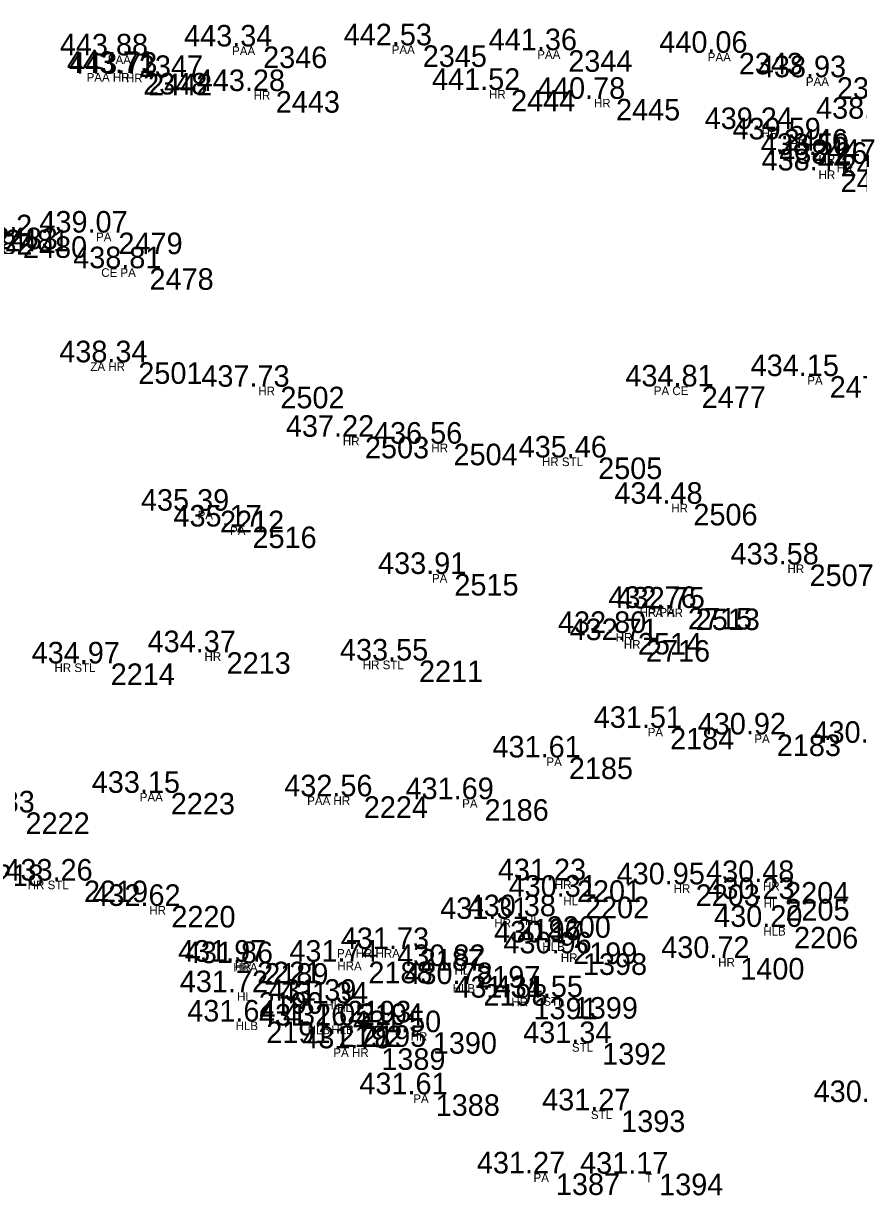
# Model space of a CAD drawing. Extents: x -639390 to -639075, y -1138747 to -1138358.
# Drawn here: x -639325.37 to -639296.34, y -1138603.09 to -1138562.34 of the extents above; entities that cross this region are included whole.
import ezdxf

# ---------------------------------------------------------------- set-up
doc = ezdxf.new("R2010")
doc.units = 0
for name, color, linetype in [('Vrstva 11', 7, 'Continuous'), ('Vrstva 12', 7, 'Continuous'), ('Vrstva 13', 7, 'Continuous'), ('Vrstva 57', 7, 'Continuous')]:
    doc.layers.add(name, color=color, linetype=linetype)

msp = doc.modelspace()

# ---------------------------------------------------------------- linework, layer by layer
at = {"layer": 'Vrstva 11'}
for p, q in [((-639317.32, -1138563.14), (-639317.32, -1138563.14)), ((-639311.77, -1138563.1), (-639311.77, -1138563.1)), ((-639321.64, -1138563.45), (-639321.64, -1138563.45)), ((-639306.71, -1138563.27), (-639306.71, -1138563.27)), ((-639300.78, -1138563.36), (-639300.78, -1138563.36)), ((-639321.49, -1138564.06), (-639321.49, -1138564.06)), ((-639321.32, -1138564.09), (-639321.32, -1138564.09)), ((-639297.37, -1138564.21), (-639297.37, -1138564.21)), ((-639316.88, -1138564.69), (-639316.88, -1138564.69)), ((-639308.7, -1138564.65), (-639308.7, -1138564.65)), ((-639305.05, -1138564.96), (-639305.05, -1138564.96)), ((-639299.22, -1138566.01), (-639299.22, -1138566.01)), ((-639298.25, -1138566.37), (-639298.25, -1138566.37)), ((-639297.24, -1138566.91), (-639297.24, -1138566.91)), ((-639296.61, -1138567.22), (-639296.61, -1138567.22)), ((-639297.24, -1138567.45), (-639297.24, -1138567.45)), ((-639322.35, -1138569.61), (-639322.35, -1138569.61)), ((-639321.27, -1138570.85), (-639321.27, -1138570.85)), ((-639321.66, -1138574.12), (-639321.66, -1138574.12)), ((-639316.72, -1138574.97), (-639316.72, -1138574.97)), ((-639302.07, -1138574.96), (-639302.07, -1138574.96)), ((-639297.62, -1138574.6), (-639297.62, -1138574.6)), ((-639313.78, -1138576.71), (-639313.78, -1138576.71)), ((-639310.7, -1138576.95), (-639310.7, -1138576.95)), ((-639305.67, -1138577.43), (-639305.67, -1138577.43)), ((-639302.36, -1138579.04), (-639302.36, -1138579.04)), ((-639318.82, -1138579.28), (-639318.82, -1138579.28)), ((-639317.69, -1138579.83), (-639317.69, -1138579.83)), ((-639310.67, -1138581.48), (-639310.67, -1138581.48)), ((-639298.32, -1138581.15), (-639298.32, -1138581.15)), ((-639302.55, -1138582.66), (-639302.55, -1138582.66)), ((-639302.28, -1138582.68), (-639302.28, -1138582.68)), ((-639304.29, -1138583.53), (-639304.29, -1138583.53)), ((-639304.01, -1138583.78), (-639304.01, -1138583.78)), ((-639318.59, -1138584.2), (-639318.59, -1138584.2)), ((-639322.62, -1138584.59), (-639322.62, -1138584.59)), ((-639311.9, -1138584.49), (-639311.9, -1138584.49)), ((-639303.17, -1138586.83), (-639303.17, -1138586.83)), ((-639299.46, -1138587.06), (-639299.46, -1138587.06)), ((-639306.69, -1138587.86), (-639306.69, -1138587.86)), ((-639320.53, -1138589.09), (-639320.53, -1138589.09)), ((-639313.82, -1138589.21), (-639313.82, -1138589.21)), ((-639309.62, -1138589.31), (-639309.62, -1138589.31)), ((-639323.55, -1138592.14), (-639323.55, -1138592.14)), ((-639306.41, -1138592.13), (-639306.41, -1138592.13)), ((-639302.28, -1138592.27), (-639302.28, -1138592.27)), ((-639299.17, -1138592.19), (-639299.17, -1138592.19)), ((-639306.13, -1138592.7), (-639306.13, -1138592.7)), ((-639299.16, -1138592.78), (-639299.16, -1138592.78)), ((-639320.51, -1138593.02), (-639320.51, -1138593.02)), ((-639308.51, -1138593.47), (-639308.51, -1138593.47)), ((-639307.46, -1138593.38), (-639307.46, -1138593.38)), ((-639298.86, -1138593.75), (-639298.86, -1138593.75)), ((-639311.87, -1138594.52), (-639311.87, -1138594.52)), ((-639306.54, -1138594.29), (-639306.54, -1138594.29)), ((-639306.2, -1138594.67), (-639306.2, -1138594.67)), ((-639300.73, -1138594.83), (-639300.73, -1138594.83)), ((-639317.53, -1138594.96), (-639317.53, -1138594.96)), ((-639317.28, -1138595.01), (-639317.28, -1138595.01)), ((-639313.66, -1138594.96), (-639313.66, -1138594.96)), ((-639309.91, -1138595.11), (-639309.91, -1138595.11)), ((-639309.66, -1138595.74), (-639309.66, -1138595.74)), ((-639317.47, -1138596.02), (-639317.47, -1138596.02)), ((-639314.4, -1138596.32), (-639314.4, -1138596.32)), ((-639313.99, -1138596.41), (-639313.99, -1138596.41)), ((-639307.92, -1138596.21), (-639307.92, -1138596.21)), ((-639306.52, -1138596.19), (-639306.52, -1138596.19)), ((-639317.21, -1138597.04), (-639317.21, -1138597.04)), ((-639314.7, -1138597.18), (-639314.7, -1138597.18)), ((-639313.88, -1138597.17), (-639313.88, -1138597.17)), ((-639311.42, -1138597.41), (-639311.42, -1138597.41)), ((-639305.53, -1138597.79), (-639305.53, -1138597.79)), ((-639313.21, -1138597.97), (-639313.21, -1138597.97)), ((-639311.32, -1138599.57), (-639311.32, -1138599.57)), ((-639304.87, -1138600.13), (-639304.87, -1138600.13)), ((-639307.14, -1138602.32), (-639307.14, -1138602.32)), ((-639303.55, -1138602.33), (-639303.55, -1138602.33))]:
    msp.add_line(p, q, dxfattribs=at)

# ---------------------------------------------------------------- texts
at = {"layer": 'Vrstva 12'}
for s, p in [('442.53 ', (-639314.239, -1138563.1)), ('443.88 ', (-639324.109, -1138563.45)), ('443.34 ', (-639319.789, -1138563.14)), ('441.36 ', (-639309.196, -1138563.27)), ('440.06 ', (-639303.266, -1138563.36)), ('443.71 ', (-639323.865, -1138564.06)), ('443.73 ', (-639323.789, -1138564.09)), ('438.93 ', (-639299.839, -1138564.21)), ('443.28 ', (-639319.349, -1138564.69)), ('441.52 ', (-639311.169, -1138564.65)), ('440.78 ', (-639307.519, -1138564.96)), ('438.31 ', (-639297.815, -1138565.65)), ('439.24 ', (-639301.689, -1138566.01)), ('439.59 ', (-639300.719, -1138566.37)), ('438.50 ', (-639299.739, -1138566.91)), ('438.44 ', (-639299.709, -1138567.45)), ('438.26 ', (-639299.096, -1138567.22)), ('439.07 ', (-639324.819, -1138569.61)), ('439.62 ', (-639328.139, -1138569.74)), ('438.81 ', (-639323.645, -1138570.85)), ('438.34 ', (-639324.129, -1138574.12)), ('434.15 ', (-639300.09, -1138574.6)), ('437.73 ', (-639319.189, -1138574.97)), ('434.81 ', (-639304.445, -1138574.96)), ('437.22 ', (-639316.249, -1138576.71)), ('436.56 ', (-639313.186, -1138576.95)), ('435.46 ', (-639308.156, -1138577.43)), ('435.39 ', (-639321.289, -1138579.28)), ('434.48 ', (-639304.829, -1138579.04)), ('435.17 ', (-639320.159, -1138579.83)), ('433.58 ', (-639300.789, -1138581.15)), ('433.91 ', (-639313.045, -1138581.48)), ('432.76 ', (-639305.036, -1138582.66)), ('432.75 ', (-639304.75, -1138582.68)), ('432.80 ', (-639306.789, -1138583.53)), ('432.71 ', (-639306.385, -1138583.78)), ('434.37 ', (-639321.059, -1138584.2)), ('434.97 ', (-639325.089, -1138584.59)), ('433.55 ', (-639314.37, -1138584.49)), ('431.51 ', (-639305.545, -1138586.83)), ('430.92 ', (-639301.929, -1138587.06)), ('430.74 ', (-639297.939, -1138587.35)), ('431.61 ', (-639309.065, -1138587.86)), ('433.15 ', (-639323, -1138589.09)), ('432.56 ', (-639316.306, -1138589.21)), ('431.69 ', (-639312.089, -1138589.31)), ('433.83 ', (-639328.049, -1138589.77)), ('433.26 ', (-639326.036, -1138592.14)), ('431.23 ', (-639308.879, -1138592.13)), ('430.95 ', (-639304.75, -1138592.27)), ('430.48 ', (-639301.639, -1138592.19)), ('430.31 ', (-639308.505, -1138592.7)), ('430.23 ', (-639301.629, -1138592.78)), ('432.62 ', (-639322.979, -1138593.02)), ('431.31 ', (-639310.885, -1138593.47)), ('430.38 ', (-639309.929, -1138593.38)), ('430.20 ', (-639301.359, -1138593.75)), ('430.17 ', (-639309.009, -1138594.29)), ('431.73 ', (-639314.339, -1138594.52)), ('430.96 ', (-639308.686, -1138594.67)), ('430.72 ', (-639303.199, -1138594.83)), ('431.97 ', (-639319.999, -1138594.96)), ('431.86 ', (-639319.766, -1138595.01)), ('431.74 ', (-639316.129, -1138594.96)), ('430.82 ', (-639312.379, -1138595.11)), ('431.72 ', (-639319.939, -1138596.02)), ('430.78 ', (-639312.129, -1138595.74)), ('431.39 ', (-639316.869, -1138596.32)), ('431.34 ', (-639316.459, -1138596.41)), ('431.34 ', (-639310.389, -1138596.21)), ('431.55 ', (-639308.99, -1138596.19)), ('431.64 ', (-639319.679, -1138597.04)), ('431.26 ', (-639317.186, -1138597.18)), ('431.05 ', (-639316.35, -1138597.17)), ('431.50 ', (-639313.919, -1138597.41)), ('431.78 ', (-639315.679, -1138597.97)), ('431.34 ', (-639307.999, -1138597.79)), ('431.61 ', (-639313.695, -1138599.57)), ('431.27 ', (-639307.339, -1138600.13)), ('430.59 ', (-639297.899, -1138599.84)), ('431.27 ', (-639309.609, -1138602.32)), ('431.17 ', (-639306.019, -1138602.33))]:
    msp.add_text(s, height=0.75, dxfattribs=at).set_placement(p)
at = {"layer": 'Vrstva 13'}
for s, p in [(' 2346', (-639317.32, -1138563.89)), (' 2345', (-639311.77, -1138563.85)), (' 2347', (-639321.64, -1138564.2)), (' 2344', (-639306.71, -1138564.02)), (' 2343', (-639300.78, -1138564.11)), (' 2348', (-639321.49, -1138564.81)), (' 2442', (-639321.32, -1138564.84)), (' 2342', (-639297.37, -1138564.96)), (' 2443', (-639316.88, -1138565.44)), (' 2444', (-639308.7, -1138565.4)), (' 2445', (-639305.05, -1138565.71)), (' 2446', (-639299.22, -1138566.76)), (' 2447', (-639298.25, -1138567.12)), (' 2448', (-639297.24, -1138567.66)), (' 2449', (-639297.24, -1138568.2)), (' 2482', (-639327.57, -1138570.38)), (' 2483', (-639326.69, -1138570.19)), (' 2481', (-639326.3, -1138570.26)), (' 2479', (-639322.35, -1138570.36)), (' 2480', (-639325.67, -1138570.49)), (' 2478', (-639321.27, -1138571.6)), (' 2501', (-639321.66, -1138574.87)), (' 2502', (-639316.72, -1138575.72)), (' 2477', (-639302.07, -1138575.71)), (' 2476', (-639297.62, -1138575.35)), (' 2503', (-639313.78, -1138577.46)), (' 2504', (-639310.7, -1138577.7)), (' 2505', (-639305.67, -1138578.18)), (' 2506', (-639302.36, -1138579.79)), (' 2212', (-639318.82, -1138580.03)), (' 2516', (-639317.69, -1138580.58)), (' 2515', (-639310.67, -1138582.23)), (' 2507', (-639298.32, -1138581.9)), (' 2715', (-639302.55, -1138583.41)), (' 2513', (-639302.28, -1138583.43)), (' 2514', (-639304.29, -1138584.28)), (' 2716', (-639304.01, -1138584.53)), (' 2213', (-639318.59, -1138584.95)), (' 2214', (-639322.62, -1138585.34)), (' 2211', (-639311.9, -1138585.24)), (' 2184', (-639303.17, -1138587.58)), (' 2183', (-639299.46, -1138587.81)), (' 2185', (-639306.69, -1138588.61)), (' 2223', (-639320.53, -1138589.84)), (' 2224', (-639313.82, -1138589.96)), (' 2186', (-639309.62, -1138590.06)), (' 2222', (-639325.58, -1138590.52)), (' 2218', (-639327.18, -1138592.33)), (' 2219', (-639323.55, -1138592.89)), (' 2201', (-639306.41, -1138592.88)), (' 2203', (-639302.28, -1138593.02)), (' 2204', (-639299.17, -1138592.94)), (' 2202', (-639306.13, -1138593.45)), (' 2205', (-639299.16, -1138593.53)), (' 2220', (-639320.51, -1138593.77)), (' 2196', (-639308.51, -1138594.22)), (' 2200', (-639307.46, -1138594.13)), (' 2206', (-639298.86, -1138594.5)), (' 2187', (-639311.87, -1138595.27)), (' 2199', (-639306.54, -1138595.04)), (' 2221', (-639317.53, -1138595.71)), (' 2188', (-639313.66, -1138595.71)), (' 1398', (-639306.2, -1138595.42)), (' 1400', (-639300.73, -1138595.58)), (' 2189', (-639317.28, -1138595.76)), (' 2197', (-639309.91, -1138595.86)), (' 2198', (-639309.66, -1138596.49)), (' 2190', (-639317.47, -1138596.77)), (' 1399', (-639306.52, -1138596.94)), (' 2193', (-639314.4, -1138597.07)), (' 2194', (-639313.99, -1138597.16)), (' 1391', (-639307.92, -1138596.96)), (' 2191', (-639317.21, -1138597.79)), (' 2192', (-639314.7, -1138597.93)), (' 2195', (-639313.88, -1138597.92)), (' 1390', (-639311.42, -1138598.16)), (' 1392', (-639305.53, -1138598.54)), (' 1389', (-639313.21, -1138598.72)), (' 1388', (-639311.32, -1138600.32)), (' 1393', (-639304.87, -1138600.88)), (' 1387', (-639307.14, -1138603.07)), (' 1394', (-639303.55, -1138603.08))]:
    msp.add_text(s, height=0.75, dxfattribs=at).set_placement(p)
at = {"layer": 'Vrstva 57'}
for s, p in [('PAA', (-639318.12, -1138563.44)), ('PAA', (-639312.57, -1138563.4)), ('PAA', (-639322.44, -1138563.75)), ('PAA', (-639307.51, -1138563.57)), ('PAA', (-639301.58, -1138563.66)), ('PAA HR', (-639323.179, -1138564.36)), ('HR', (-639321.809, -1138564.39)), ('PAA', (-639298.17, -1138564.51)), ('HR', (-639317.369, -1138564.99)), ('HR', (-639309.189, -1138564.95)), ('HR', (-639305.539, -1138565.26)), ('HR', (-639299.709, -1138566.31)), ('HR', (-639298.739, -1138566.67)), ('HR', (-639297.729, -1138567.21)), ('HR', (-639297.099, -1138567.52)), ('HR', (-639297.729, -1138567.75)), ('PA', (-639322.85, -1138569.91)), ('CE PA', (-639322.67, -1138571.15)), ('ZA HR', (-639323.049, -1138574.42)), ('HR', (-639317.209, -1138575.27)), ('PA CE', (-639303.458, -1138575.26)), ('PA', (-639298.12, -1138574.9)), ('HR', (-639314.269, -1138577.01)), ('HR', (-639311.189, -1138577.25)), ('HR STL', (-639307.345, -1138577.73)), ('HR', (-639302.849, -1138579.34)), ('PA', (-639319.32, -1138579.58)), ('PA', (-639318.19, -1138580.13)), ('PA', (-639311.17, -1138581.78)), ('HR', (-639298.809, -1138581.45)), ('HR PA', (-639303.95, -1138582.96)), ('PA HR', (-639303.669, -1138582.98)), ('HR', (-639304.779, -1138583.83)), ('HR', (-639304.499, -1138584.08)), ('HR', (-639319.079, -1138584.5)), ('HR STL', (-639324.295, -1138584.89)), ('HR STL', (-639313.575, -1138584.79)), ('PA', (-639303.67, -1138587.13)), ('PA', (-639299.96, -1138587.36)), ('PA', (-639307.19, -1138588.16)), ('PAA', (-639321.33, -1138589.39)), ('PAA HR', (-639315.509, -1138589.51)), ('PA', (-639310.12, -1138589.61)), ('HR STL', (-639325.225, -1138592.44)), ('HR', (-639306.899, -1138592.43)), ('HR', (-639302.769, -1138592.57)), ('HR', (-639299.659, -1138592.49)), ('HL', (-639306.605, -1138593)), ('HL', (-639299.635, -1138593.08)), ('HR', (-639320.999, -1138593.32)), ('HR', (-639308.999, -1138593.77)), ('HL', (-639307.935, -1138593.68)), ('HLB', (-639299.649, -1138594.05)), ('PA HR HRA', (-639314.47, -1138594.82)), ('HLB', (-639307.329, -1138594.59)), ('HR', (-639306.689, -1138594.97)), ('HR', (-639301.219, -1138595.13)), ('HRA', (-639318.08, -1138595.31)), ('HR', (-639318.019, -1138595.26)), ('HRA', (-639314.46, -1138595.26)), ('HL', (-639310.385, -1138595.41)), ('HLB', (-639310.449, -1138596.04)), ('HL', (-639317.945, -1138596.32)), ('HL', (-639314.875, -1138596.62)), ('HL', (-639314.465, -1138596.71)), ('HR', (-639308.409, -1138596.51)), ('STL', (-639307.295, -1138596.49)), ('HLB', (-639317.999, -1138597.34)), ('HLB', (-639315.489, -1138597.48)), ('HLB', (-639314.669, -1138597.47)), ('HR', (-639311.909, -1138597.71)), ('STL', (-639306.305, -1138598.09)), ('PA HR', (-639314.599, -1138598.27)), ('PA', (-639311.82, -1138599.87)), ('STL', (-639305.645, -1138600.43)), ('PA', (-639307.64, -1138602.62)), ('T', (-639303.75, -1138602.63))]:
    msp.add_text(s, height=0.3, dxfattribs=at).set_placement(p)

doc.saveas('drawing.dxf')
